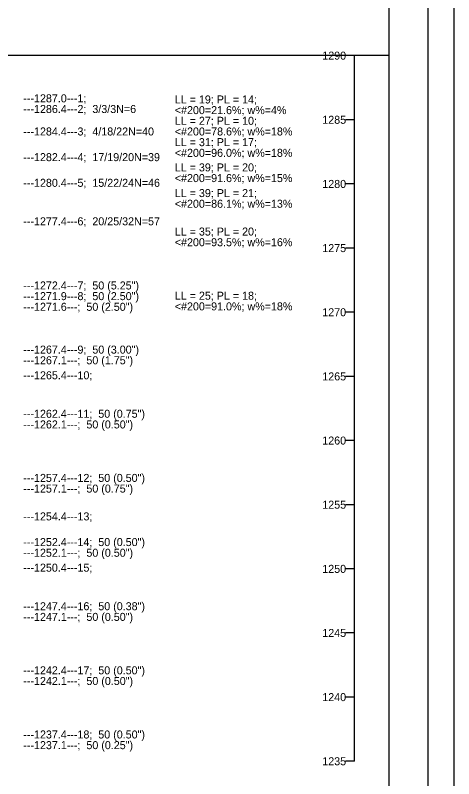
# Model space of a CAD drawing. Extents: x 2150148.6 to 2150220.1, y 143803.7 to 143875.1.
# Drawn here: x 2150203.38 to 2150211.6, y 143845.54 to 143859.84 of the extents above; entities that cross this region are included whole.
import ezdxf

# ---------------------------------------------------------------- set-up
doc = ezdxf.new("R2010")
doc.units = 0
for name, color, linetype in [('Default', 7, 'Continuous'), ('SHT_Plot_Shape_Full', 7, 'Continuous'), ('SHT_Plot_Shape_Half', 7, 'Continuous'), ('SHT_Sheet_Border', 7, 'Continuous')]:
    doc.layers.add(name, color=color, linetype=linetype)

msp = doc.modelspace()

# ---------------------------------------------------------------- linework, layer by layer
at = {"layer": 'Default'}
msp.add_line((2150209.738, 143845.865), (2150209.738, 143859.086), dxfattribs=at)
for points in [[(2150209.738, 143859.086), (2150209.572, 143859.086)], [(2150209.738, 143857.884), (2150209.572, 143857.884)], [(2150209.738, 143856.682), (2150209.572, 143856.682)], [(2150209.738, 143855.48), (2150209.572, 143855.48)], [(2150209.738, 143854.278), (2150209.572, 143854.278)], [(2150209.738, 143853.076), (2150209.572, 143853.076)], [(2150209.738, 143851.874), (2150209.572, 143851.874)], [(2150209.738, 143850.672), (2150209.572, 143850.672)], [(2150209.738, 143849.47), (2150209.572, 143849.47)], [(2150209.738, 143848.269), (2150209.572, 143848.269)], [(2150209.738, 143847.067), (2150209.572, 143847.067)], [(2150209.738, 143845.865), (2150209.572, 143845.865)]]:
    msp.add_lwpolyline(points, dxfattribs=at)
at = {"layer": 'Defpoints'}
msp.add_line((2150210.379, 143859.086), (2150168.379, 143859.086), dxfattribs=at)
at = {"layer": 'SHT_Plot_Shape_Full'}
msp.add_lwpolyline([(2150163.596, 143867.587), (2150211.596, 143867.587), (2150211.596, 143835.587), (2150163.596, 143835.587)], close=True, dxfattribs=at)
at = {"layer": 'SHT_Plot_Shape_Half'}
msp.add_lwpolyline([(2150165.779, 143866.487), (2150211.112, 143866.487), (2150211.112, 143837.154), (2150165.779, 143837.154)], close=True, dxfattribs=at)
at = {"layer": 'SHT_Sheet_Border'}
msp.add_lwpolyline([(2150210.379, 143837.82), (2150168.379, 143837.82), (2150168.379, 143865.82), (2150210.379, 143865.82)], close=True, dxfattribs=at)

# ---------------------------------------------------------------- texts
at = {"layer": 'Default'}
for s, p in [('1290', (2150209.134, 143859.011)), ('---1287.0---1;', (2150203.535, 143858.211)), ('LL = 19; PL = 14;', (2150206.372, 143858.19)), ('---1286.4---2;  3/3/3N=6', (2150203.535, 143858.011)), ('<#200=21.6%; w%=4%', (2150206.372, 143857.99)), ('LL = 27; PL = 10;', (2150206.372, 143857.79)), ('1285', (2150209.134, 143857.809)), ('---1284.4---3;  4/18/22N=40', (2150203.535, 143857.59)), ('<#200=78.6%; w%=18%', (2150206.372, 143857.59)), ('LL = 31; PL = 17;', (2150206.372, 143857.39)), ('---1282.4---4;  17/19/20N=39', (2150203.535, 143857.109)), ('<#200=96.0%; w%=18%', (2150206.372, 143857.19)), ('LL = 39; PL = 20;', (2150206.372, 143856.917)), ('<#200=91.6%; w%=15%', (2150206.372, 143856.717)), ('---1280.4---5;  15/22/24N=46', (2150203.535, 143856.628)), ('1280', (2150209.134, 143856.607)), ('LL = 39; PL = 21;', (2150206.372, 143856.436)), ('<#200=86.1%; w%=13%', (2150206.372, 143856.236)), ('---1277.4---6;  20/25/32N=57', (2150203.535, 143855.907)), ('LL = 35; PL = 20;', (2150206.372, 143855.715)), ('<#200=93.5%; w%=16%', (2150206.372, 143855.515)), ('1275', (2150209.134, 143855.405)), ('---1272.4---7;  50 (5.25")', (2150203.535, 143854.705)), ('---1271.9---8;  50 (2.50")', (2150203.535, 143854.505)), ('LL = 25; PL = 18;', (2150206.372, 143854.513)), ('---1271.6---;  50 (2.50")', (2150203.535, 143854.305)), ('<#200=91.0%; w%=18%', (2150206.372, 143854.313)), ('1270', (2150209.134, 143854.203)), ('---1267.4---9;  50 (3.00")', (2150203.535, 143853.503)), ('---1267.1---;  50 (1.75")', (2150203.535, 143853.303)), ('---1265.4---10;', (2150203.535, 143853.022)), ('1265', (2150209.134, 143853.001)), ('---1262.4---11;  50 (0.75")', (2150203.535, 143852.301)), ('---1262.1---;  50 (0.50")', (2150203.535, 143852.101)), ('1260', (2150209.134, 143851.799)), ('---1257.4---12;  50 (0.50")', (2150203.535, 143851.099)), ('---1257.1---;  50 (0.75")', (2150203.535, 143850.899)), ('1255', (2150209.134, 143850.597)), ('---1254.4---13;', (2150203.535, 143850.378)), ('---1252.4---14;  50 (0.50")', (2150203.535, 143849.897)), ('---1252.1---;  50 (0.50")', (2150203.535, 143849.697)), ('---1250.4---15;', (2150203.535, 143849.417)), ('1250', (2150209.134, 143849.395)), ('---1247.4---16;  50 (0.38")', (2150203.535, 143848.695)), ('---1247.1---;  50 (0.50")', (2150203.535, 143848.495)), ('1245', (2150209.134, 143848.194)), ('---1242.4---17;  50 (0.50")', (2150203.535, 143847.494)), ('---1242.1---;  50 (0.50")', (2150203.535, 143847.294)), ('1240', (2150209.134, 143846.992)), ('---1237.4---18;  50 (0.50")', (2150203.535, 143846.292)), ('---1237.1---;  50 (0.25")', (2150203.535, 143846.092)), ('1235', (2150209.134, 143845.79))]:
    msp.add_text(s, height=0.15, dxfattribs=at).set_placement(p)

doc.saveas('drawing.dxf')
